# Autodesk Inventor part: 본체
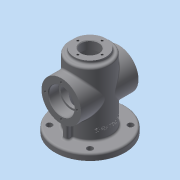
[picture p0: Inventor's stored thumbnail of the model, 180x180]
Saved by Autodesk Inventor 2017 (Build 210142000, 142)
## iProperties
Created: 2020-05
Part Number: 본체
Material: 알루미늄 6061
Document SubType Name: Modeling
Designer: mduedu
Density: 2.7 g/cm^3
Appearance: 기본값
Mass: 774.387 g
Surface Area: 687.925 cm^2
Volume: 286.81 cm^3
Author: mduedu
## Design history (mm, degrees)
sketch "스케치1"
  geometry: C1 r 32 at (0, 0); 1 further point
  constraints: 1 centre point, 1 coincident
  dimensions: "d0" = 64 diameter of C1
extrude "돌출1" new body sketch "스케치1" distance "d1" = 110; taper "d2" = 0 deg
feature "쉘1" dims "d3" = 8
fillet "모깎기1" dims "d4" = 3
fillet "모깎기2" dims "d5" = 3
sketch "스케치2"
  geometry: C1 r 25 at (0, 0); 1 further point
  constraints: 1 centre point, 1 coincident
  dimensions: "d6" = 50 diameter of C1
extrude "돌출2" join sketch "스케치2" distance "d7" = 5; taper "d8" = 0 deg
sketch "스케치3"
  geometry: C1 r 14 at (0, 0); 1 further point
  constraints: 1 centre point, 1 coincident
  dimensions: "d9" = 28 diameter of C1
extrude "돌출3" cut sketch "스케치3" stored distance "d10" = 5; taper "d11" = 0 deg
fillet "모깎기3" dims "d12" = 3
sketch "스케치4"
  geometry: C1 r 32 at (0, 0) reference; C2 r 55 at (0, 0); 1 further point
  constraints: 1 centre point, 1 coincident
  dimensions: "d13" = 110 diameter of C2
extrude "돌출4" join sketch "스케치4" distance "d14" = 10; taper "d15" = 0 deg
sketch "스케치5"
  geometry: L1 (0, 0)-(-31.82, 31.82); L2 (0, 0)-(-45, 0); A1 r 45 centre (0, 0) between (-31.82, 31.82) and (-45, 0); 1 further point
  constraints: 4 end point, 2 point on circle, 1 centre point, 1 coincident, 1 horizontal
  dimensions: "d16" = 90 diameter of A1; "d71" = 45 deg angle of L1 L2
hole "구멍1" sketch "스케치5" at (-31.82, 31.82) diameter "d17" = 9; stored, may be unused: countersink angle "d21" = 90 deg, drill point angle "d23" = 118 deg; dims "d18" = 6, "d19" = 4, "d20" = 2, "d22" = 8
fillet "모깎기4" dims "d27" = 3
node "작업 평면1"
sketch "스케치6"
  geometry: L1 (0, 55)-(0, -55) reference; C1 r 31 at (-65, 0); 2 further points
  constraints: 1 centre point, 1 horizontal alignment, 1 midpoint
  dimensions: "d31" = 62 diameter of C1; "d32" = 65 distance from line of C1.centre L1
extrude "돌출5" join sketch "스케치6" stored distance "d33" = 10; taper "d34" = 0 deg
fillet "모깎기5" dims "d35" = 3
sketch "스케치7"
  geometry: C1 r 31 at (0, 0) reference; C2 r 20 at (0, 0); 1 further point
  constraints: 1 centre point, 1 coincident
  dimensions: "d36" = 40 diameter of C2
extrude "돌출6" cut sketch "스케치7" distance "d37" = 16; taper "d38" = 0 deg
sketch "스케치8"
  geometry: C1 r 20 at (0, 0) reference; C2 r 17 at (0, 0); 1 further point
  constraints: 1 centre point, 1 coincident
  dimensions: "d39" = 34 diameter of C2
extrude "돌출7" cut sketch "스케치8" stored distance "d40" = 15; taper "d41" = 0 deg
fillet "모깎기6" dims "d42" = 0.3
chamfer "모따기1" distance "d43" = 1; stored, may be unused: second distance "d44" = 2, angle "d45" = 45 deg
chamfer "모따기2" distance "d46" = 1; stored, may be unused: second distance "d47" = 2, angle "d48" = 45 deg
sketch "스케치9" dims "d49" = 50
  geometry: C1 r 31 at (0, 0) reference; 3 further points
  constraints: 2 vertical alignment, 1 coincident, 2 other
hole "구멍2" sketch "스케치9" at (0, 25) diameter "d50" = 3.242; stored, may be unused: countersink angle "d54" = 90 deg, drill point angle "d56" = 118 deg; dims "d51" = 7, "d52" = 4, "d53" = 2, "d55" = 9
sketch "스케치10" dims "d60" = 38
  geometry: 3 further points
  constraints: 2 vertical alignment, 1 coincident, 2 other
hole "구멍3" sketch "스케치10" at (0, 19) diameter "d61" = 3.242; stored, may be unused: countersink angle "d65" = 90 deg, drill point angle "d67" = 118 deg; dims "d62" = 8, "d63" = 4, "d64" = 2, "d66" = 10
sketch "스케치11"
  geometry: L1 (32, 31)-(32, 13) reference; L2 (35, 10)-(52, 10) reference; L3 (55, 7)-(55, 0) reference; L4 (55, 0)-(24, 0) reference; L5 (24, 0)-(24, 48) reference; L6 (24, 48)-(29, 48) reference; L7 (29, 48)-(29, 45.3) reference; L8 (29.3, 45)-(44, 45) reference; L9 (44, 45)-(45, 44) reference; L10 (45, 44)-(45, 41.621) reference; L11 (45, 41.621)-(36, 41.621) reference; L12 (36, 41.621)-(35.026, 40) reference; L13 (35.026, 40)-(36, 38.379) reference; L14 (36, 38.379)-(45, 38.379) reference; L15 (45, 38.379)-(45, 34) reference; L16 (45, 34)-(35, 34) reference; L17 (-32, 13)-(-32, 31) reference; L18 (-35, 34)-(-45, 34) reference; L19 (-45, 34)-(-45, 38.379) reference; L20 (-45, 38.379)-(-36, 38.379) reference; L21 (-36, 38.379)-(-35.026, 40) reference; L22 (-35.026, 40)-(-36, 41.621) reference; L23 (-36, 41.621)-(-45, 41.621) reference; L24 (-45, 41.621)-(-45, 44) reference; L25 (-45, 44)-(-44, 45) reference; L26 (-44, 45)-(-29.3, 45) reference; L27 (-29, 45.3)-(-29, 48) reference; L28 (-29, 48)-(-24, 48) reference; L29 (-24, 48)-(-24, 0) reference; L30 (-24, 0)-(-55, 0) reference; L31 (-55, 0)-(-55, 7) reference; L32 (-52, 10)-(-35, 10) reference; L33 (-25, 113)-(-25, 115) reference; L34 (-25, 115)-(-20.621, 115) reference; L35 (-20.621, 115)-(-20.621, 105) reference; L36 (-20.621, 105)-(-19, 104.026) reference; L37 (-19, 104.026)-(-17.379, 105) reference; L38 (-17.379, 105)-(-17.379, 115) reference; L39 (-17.379, 115)-(-15, 115) reference; L40 (-15, 115)-(-14, 114) reference; L41 (-14, 114)-(-14, 102) reference; L42 (-14, 102)-(-21, 102) reference; L43 (-24, 99)-(-24, 82) reference; L44 (-24, 82)-(-29, 82) reference; L45 (-29, 82)-(-29, 84.7) reference; L46 (-29.3, 85)-(-44, 85) reference; L47 (-44, 85)-(-45, 86) reference; L48 (-45, 86)-(-45, 88.379) reference; L49 (-45, 88.379)-(-36, 88.379) reference; L50 (-36, 88.379)-(-35.026, 90) reference; L51 (-35.026, 90)-(-36, 91.621) reference; L52 (-36, 91.621)-(-45, 91.621) reference; L53 (-45, 91.621)-(-45, 96) reference; L54 (-45, 96)-(-35, 96) reference; L55 (-32, 99)-(-32, 107) reference; L56 (-29, 110)-(-28, 110) reference; L57 (28, 110)-(29, 110) reference; L58 (32, 107)-(32, 99) reference; L59 (35, 96)-(45, 96) reference; L60 (45, 96)-(45, 91.621) reference; L61 (45, 91.621)-(36, 91.621) reference; L62 (36, 91.621)-(35.026, 90) reference; L63 (35.026, 90)-(36, 88.379) reference; L64 (36, 88.379)-(45, 88.379) reference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; A1 r 3 centre (35, 13) between (32, 13) and (35, 10) reference; A2 r 3 centre (52, 7) between (55, 7) and (52, 10) reference; A3 r 0.3 centre (29.3, 45.3) between (29, 45.3) and (29.3, 45) reference; A4 r 0.3 centre (-29.3, 45.3) between (-29.3, 45) and (-29, 45.3) reference; A5 r 3 centre (-52, 7) between (-52, 10) and (-55, 7) reference; A6 r 3 centre (-35, 13) between (-35, 10) and (-32, 13) reference; A7 r 3 centre (-28, 113) between (-28, 110) and (-25, 113) reference; A8 r 3 centre (-21, 99) between (-21, 102) and (-24, 99) reference; A9 r 0.3 centre (-29.3, 84.7) between (-29, 84.7) and (-29.3, 85) reference; A10 r 3 centre (-29, 107) between (-29, 110) and (-32, 107) reference; A11 r 3 centre (28, 113) between (25, 113) and (28, 110) reference; A12 r 3 centre (29, 107) between (32, 107) and (29, 110) reference; A13 r 0.3 centre (29.3, 84.7) between (29.3, 85) and (29, 84.7) reference; A14 r 3 centre (21, 99) between (24, 99) and (21, 102) reference; 1 further point
  constraints: 2 end point, 1 midpoint, 1 perpendicular, 1 point on line, 4 other
  dimensions: "d73" = 5 distance between parallel lines of L81 L19
feature "리브1" sketch "스케치11" dims "d74" = 1, "d75" = 8, "d76" = 0, "d77" = 0, "d78" = 1, "d79" = 1
fillet "모깎기7" dims "d80" = 3
fillet "모깎기8" dims "d81" = 3
node "작업 평면2"
sketch "스케치12"
  geometry: 2 further points
  constraints: 1 vertical alignment, 1 other
  dimensions: "d83" = 25 distance of point (0, 25) point (0, 0)
feature "엠보싱1" sketch "스케치12" dims "d0" = 64, "d84" = 0.5, "d85" = 0
node "솔리드1"
pattern_circular "원형 패턴1" dims angle "d25" = 360 deg
mirror "대칭1"
mirror "대칭2"
pattern_circular "원형 패턴2" dims angle "d58" = 360 deg
mirror "대칭3"
pattern_circular "원형 패턴3" dims angle "d69" = 360 deg
mirror "대칭4"
node "투영된 루프1"
node "투영된 루프2"
node "절단 모서리 투영1"
other parameters: "d30" = -45
